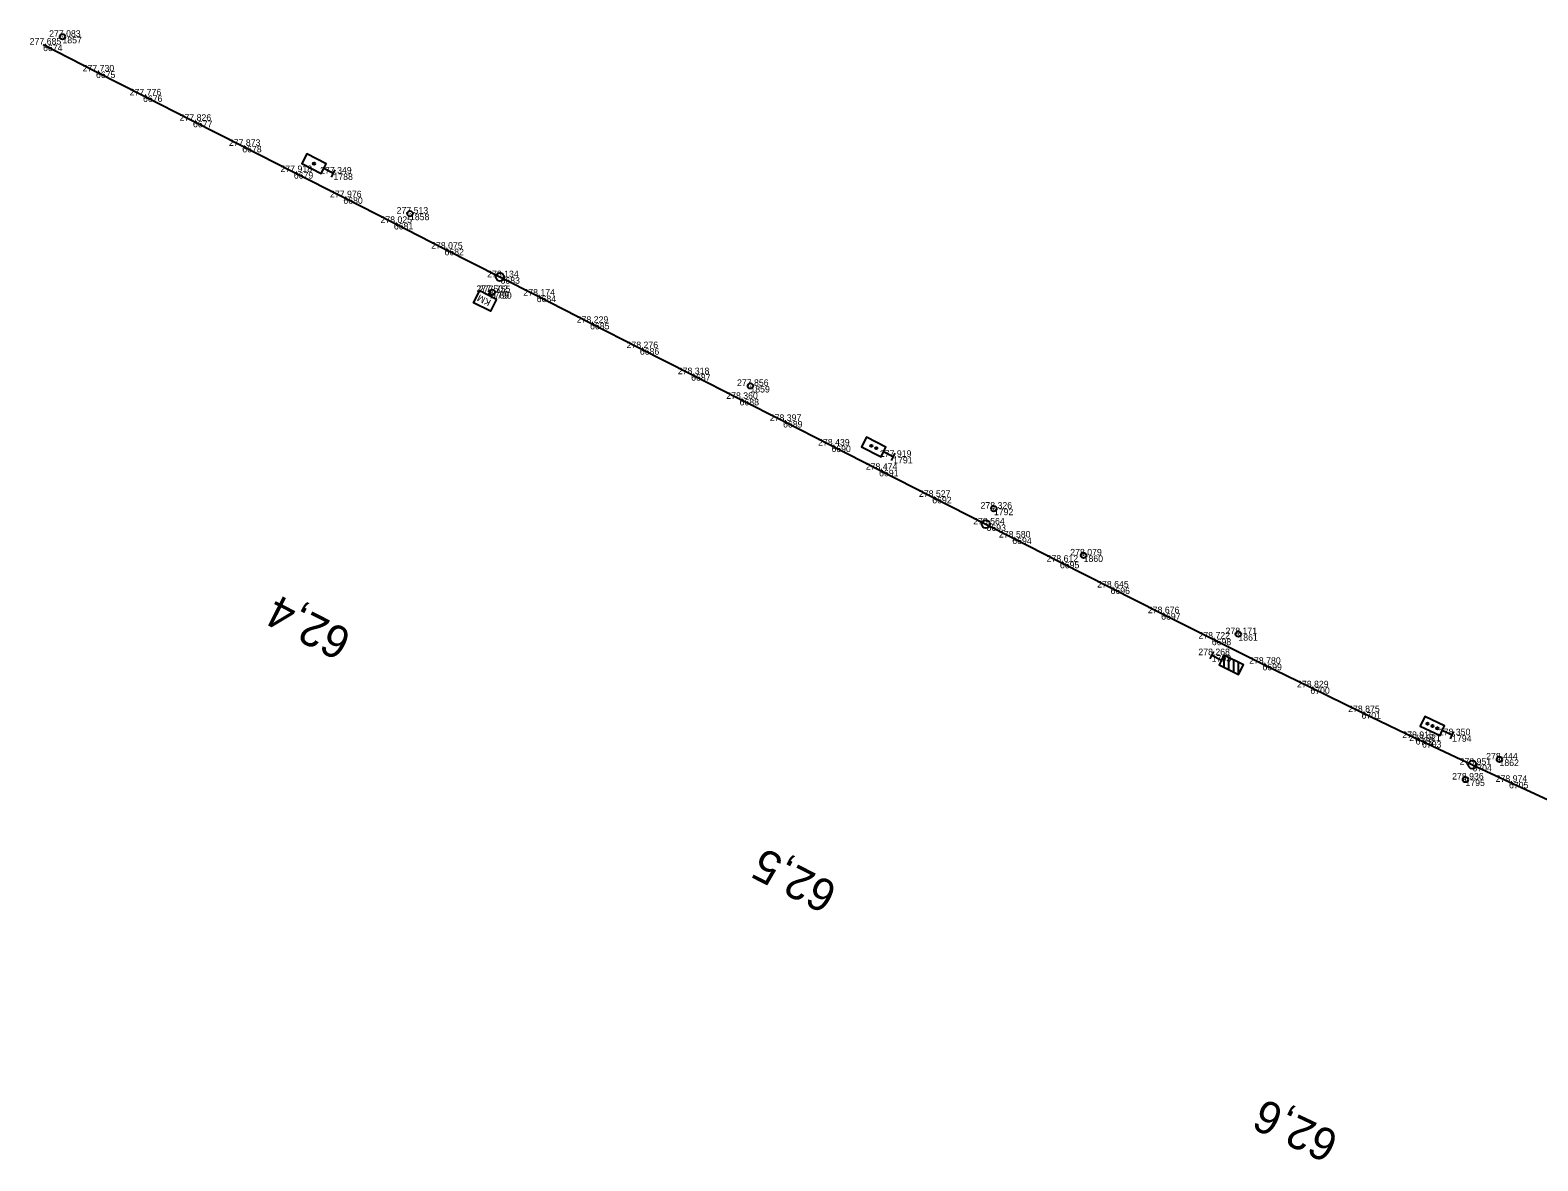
# Model space of a CAD drawing. Extents: x -613968 to -612840, y -1056667 to -1056202.
# Drawn here: x -613967.8 to -613690.5, y -1056410.2 to -1056202.3 of the extents above; entities that cross this region are included whole.
import ezdxf

# ---------------------------------------------------------------- set-up
doc = ezdxf.new("R2010")
doc.units = 0
for name, color, linetype in [('Rozpiska_pole_7', 7, 'Continuous'), ('Vrstva 1', 7, 'Continuous'), ('Vrstva 50', 7, 'Continuous'), ('Vrstva 60', 7, 'Continuous'), ('Vrstva 61', 7, 'Continuous')]:
    doc.layers.add(name, color=color, linetype=linetype)

msp = doc.modelspace()

# ---------------------------------------------------------------- linework, layer by layer
at = {"layer": 'Rozpiska_pole_7'}
for p, q in [((-613915.67, -1056226.63), (-613915.54, -1056227.01)), ((-613912.38, -1056229.3), (-613911.7, -1056227.97)), ((-613883.3, -1056250.41), (-613883.58, -1056250.96)), ((-613882.89, -1056250.43), (-613882.8, -1056250.47)), ((-613813.17, -1056278.5), (-613813.05, -1056278.88)), ((-613812.29, -1056278.96), (-613812.17, -1056279.34)), ((-613809.44, -1056281.4), (-613808.76, -1056280.06)), ((-613790.63, -1056290.23), (-613790.54, -1056290.28)), ((-613750.19, -1056316.52), (-613750.86, -1056317.86)), ((-613748.29, -1056317.18), (-613748.28, -1056319.42)), ((-613747.38, -1056319.86), (-613747.39, -1056317.63)), ((-613746.49, -1056318.07), (-613746.49, -1056320.31)), ((-613745.59, -1056320.75), (-613745.6, -1056318.52)), ((-613710.91, -1056329.59), (-613710.77, -1056329.97)), ((-613709.99, -1056330.02), (-613709.86, -1056330.39)), ((-613709.09, -1056330.44), (-613708.95, -1056330.82)), ((-613706.63, -1056332.59), (-613705.99, -1056331.23)), ((-613703.91, -1056340.03), (-613703.82, -1056340.07))]:
    msp.add_line(p, q, dxfattribs=at)
for points in [[(-613912.04, -1056228.64), (-613913.82, -1056227.73), (-613913.37, -1056226.84), (-613916.94, -1056225.02), (-613917.84, -1056226.81), (-613914.28, -1056228.62), (-613913.82, -1056227.73)], [(-613809.1, -1056280.73), (-613810.88, -1056279.82), (-613810.43, -1056278.93), (-613814, -1056277.12), (-613814.9, -1056278.9), (-613811.34, -1056280.72), (-613810.88, -1056279.82)], [(-613750.52, -1056317.19), (-613748.73, -1056318.08), (-613749.18, -1056318.97), (-613745.59, -1056320.75), (-613744.7, -1056318.96), (-613748.29, -1056317.18), (-613748.73, -1056318.08)], [(-613706.31, -1056331.91), (-613708.12, -1056331.05), (-613707.69, -1056330.15), (-613711.31, -1056328.45), (-613712.16, -1056330.25), (-613708.54, -1056331.96), (-613708.12, -1056331.05)]]:
    msp.add_lwpolyline(points, dxfattribs=at)
msp.add_lwpolyline([(-613882.03, -1056251.75), (-613883.16, -1056253.96), (-613886.27, -1056252.38), (-613885.14, -1056250.17)], close=True, dxfattribs=at)
for centre, radius in [((-613915.61, -1056226.82), 0.2), ((-613881.42, -1056247.65), 0.75), ((-613882.84, -1056250.45), 0.5), ((-613813.11, -1056278.69), 0.2), ((-613812.22, -1056279.14), 0.2), ((-613792.06, -1056293.09), 0.75), ((-613790.58, -1056290.25), 0.5), ((-613710.83, -1056329.78), 0.2), ((-613709.93, -1056330.2), 0.2), ((-613709.02, -1056330.63), 0.2), ((-613702.61, -1056337.33), 0.75), ((-613703.86, -1056340.05), 0.5)]:
    msp.add_circle(centre, radius, dxfattribs=at)
at = {"layer": 'Vrstva 1'}
msp.add_lwpolyline([(-613965.44, -1056204.93), (-613955.71, -1056209.87), (-613947.06, -1056214.27), (-613937.88, -1056218.94), (-613928.81, -1056223.55), (-613919.33, -1056228.37), (-613910.22, -1056233), (-613900.93, -1056237.72), (-613891.62, -1056242.46), (-613881.32, -1056247.7), (-613874.66, -1056251.08), (-613864.85, -1056256.08), (-613855.69, -1056260.74), (-613846.26, -1056265.53), (-613837.35, -1056270.06), (-613829.35, -1056274.13), (-613820.46, -1056278.65), (-613811.69, -1056283.11), (-613801.92, -1056288.08), (-613791.94, -1056293.16), (-613787.2, -1056295.56), (-613778.44, -1056300.01), (-613769.13, -1056304.75), (-613759.82, -1056309.47), (-613750.51, -1056314.15), (-613741.19, -1056318.77), (-613732.38, -1056323.1), (-613722.97, -1056327.66), (-613713.02, -1056332.42), (-613711.85, -1056332.98), (-613702.58, -1056337.34), (-613695.85, -1056340.48), (-613686.37, -1056344.84)], dxfattribs=at)
at = {"layer": 'Vrstva 50'}
for p, q in [((-613961.93, -1056203.47), (-613961.84, -1056203.52)), ((-613898.01, -1056235.99), (-613897.92, -1056236.04)), ((-613835.41, -1056267.67), (-613835.32, -1056267.71)), ((-613774.13, -1056298.83), (-613774.04, -1056298.87)), ((-613745.67, -1056313.3), (-613745.58, -1056313.34)), ((-613697.65, -1056336.34), (-613697.55, -1056336.38))]:
    msp.add_line(p, q, dxfattribs=at)
for centre in [(-613961.88, -1056203.5), (-613897.97, -1056236.01), (-613835.36, -1056267.69), (-613774.08, -1056298.85), (-613745.62, -1056313.32), (-613697.6, -1056336.36)]:
    msp.add_circle(centre, 0.5, dxfattribs=at)
at = {"layer": 'Vrstva 60'}
for p, q in [((-613961.88, -1056203.5), (-613961.88, -1056203.5)), ((-613965.44, -1056204.93), (-613965.44, -1056204.93)), ((-613955.71, -1056209.87), (-613955.71, -1056209.87)), ((-613947.06, -1056214.27), (-613947.06, -1056214.27)), ((-613937.88, -1056218.94), (-613937.88, -1056218.94)), ((-613928.81, -1056223.55), (-613928.81, -1056223.55)), ((-613919.33, -1056228.37), (-613919.33, -1056228.37)), ((-613912.04, -1056228.64), (-613912.04, -1056228.64)), ((-613910.22, -1056233), (-613910.22, -1056233)), ((-613897.97, -1056236.01), (-613897.97, -1056236.01)), ((-613900.93, -1056237.72), (-613900.93, -1056237.72)), ((-613891.62, -1056242.46), (-613891.62, -1056242.46)), ((-613881.32, -1056247.7), (-613881.32, -1056247.7)), ((-613883.3, -1056250.41), (-613883.3, -1056250.41)), ((-613882.84, -1056250.45), (-613882.84, -1056250.45)), ((-613874.66, -1056251.08), (-613874.66, -1056251.08)), ((-613864.85, -1056256.08), (-613864.85, -1056256.08)), ((-613855.69, -1056260.74), (-613855.69, -1056260.74)), ((-613846.26, -1056265.53), (-613846.26, -1056265.53)), ((-613837.35, -1056270.06), (-613837.35, -1056270.06)), ((-613835.36, -1056267.69), (-613835.36, -1056267.69)), ((-613829.35, -1056274.13), (-613829.35, -1056274.13)), ((-613820.46, -1056278.65), (-613820.46, -1056278.65)), ((-613809.1, -1056280.73), (-613809.1, -1056280.73)), ((-613811.69, -1056283.11), (-613811.69, -1056283.11)), ((-613801.92, -1056288.08), (-613801.92, -1056288.08)), ((-613790.58, -1056290.25), (-613790.58, -1056290.25)), ((-613791.94, -1056293.16), (-613791.94, -1056293.16)), ((-613787.2, -1056295.56), (-613787.2, -1056295.56)), ((-613778.44, -1056300.01), (-613778.44, -1056300.01)), ((-613774.08, -1056298.85), (-613774.08, -1056298.85)), ((-613769.13, -1056304.75), (-613769.13, -1056304.75)), ((-613759.82, -1056309.47), (-613759.82, -1056309.47)), ((-613750.51, -1056314.15), (-613750.51, -1056314.15)), ((-613745.62, -1056313.32), (-613745.62, -1056313.32)), ((-613750.52, -1056317.19), (-613750.52, -1056317.19)), ((-613741.19, -1056318.77), (-613741.19, -1056318.77)), ((-613732.38, -1056323.1), (-613732.38, -1056323.1)), ((-613722.97, -1056327.66), (-613722.97, -1056327.66)), ((-613713.02, -1056332.42), (-613713.02, -1056332.42)), ((-613711.85, -1056332.98), (-613711.85, -1056332.98)), ((-613706.31, -1056331.91), (-613706.31, -1056331.91)), ((-613697.6, -1056336.36), (-613697.6, -1056336.36)), ((-613702.58, -1056337.34), (-613702.58, -1056337.34)), ((-613703.86, -1056340.05), (-613703.86, -1056340.05)), ((-613695.85, -1056340.48), (-613695.85, -1056340.48))]:
    msp.add_line(p, q, dxfattribs=at)

# ---------------------------------------------------------------- texts
at = {"layer": 'Rozpiska_pole_7'}
for s, height, rotation, p in [('KM', 1.247, 153.0609, (-613882.96, -1056251.97)), ('62,4', 6, 153.0609, (-613908.34, -1056313.01)), ('62,5', 6, 153.0346, (-613819.01, -1056359.54)), ('62,6', 6, 154.7757, (-613726.8, -1056405.26))]:
    msp.add_text(s, height=height, rotation=rotation, dxfattribs=at).set_placement(p)
at = {"layer": 'Vrstva 60'}
for s, p in [('1857', (-613961.88, -1056204.7)), ('6674', (-613965.44, -1056206.13)), ('6675', (-613955.71, -1056211.07)), ('6676', (-613947.06, -1056215.47)), ('6677', (-613937.88, -1056220.14)), ('6678', (-613928.81, -1056224.75)), ('6679', (-613919.33, -1056229.57)), ('1788', (-613912.04, -1056229.83)), ('6680', (-613910.22, -1056234.2)), ('1858', (-613897.97, -1056237.21)), ('6681', (-613900.93, -1056238.92)), ('6682', (-613891.62, -1056243.66)), ('6683', (-613881.32, -1056248.9)), ('1789', (-613883.3, -1056251.61)), ('1790', (-613882.84, -1056251.65)), ('6684', (-613874.66, -1056252.28)), ('6685', (-613864.85, -1056257.28)), ('6686', (-613855.69, -1056261.94)), ('6687', (-613846.26, -1056266.73)), ('6688', (-613837.35, -1056271.26)), ('1859', (-613835.36, -1056268.89)), ('6689', (-613829.35, -1056275.33)), ('6690', (-613820.46, -1056279.85)), ('1791', (-613809.1, -1056281.93)), ('6691', (-613811.69, -1056284.31)), ('6692', (-613801.92, -1056289.28)), ('1792', (-613790.58, -1056291.45)), ('6693', (-613791.94, -1056294.36)), ('6694', (-613787.2, -1056296.76)), ('6695', (-613778.44, -1056301.21)), ('1860', (-613774.08, -1056300.05)), ('6696', (-613769.13, -1056305.95)), ('6697', (-613759.82, -1056310.67)), ('6698', (-613750.51, -1056315.35)), ('1861', (-613745.62, -1056314.52)), ('1793', (-613750.52, -1056318.39)), ('6699', (-613741.19, -1056319.97)), ('6700', (-613732.38, -1056324.3)), ('6701', (-613722.97, -1056328.86)), ('6702', (-613713.02, -1056333.62)), ('6703', (-613711.85, -1056334.18)), ('1794', (-613706.31, -1056333.11)), ('1862', (-613697.6, -1056337.56)), ('6704', (-613702.58, -1056338.54)), ('1795', (-613703.86, -1056341.25)), ('6705', (-613695.85, -1056341.68))]:
    msp.add_text(s, height=1.2, dxfattribs=at).set_placement(p)
at = {"layer": 'Vrstva 61'}
for s, p in [('277.685', (-613967.9, -1056204.93)), ('277.083', (-613964.33, -1056203.5)), ('277.730', (-613958.16, -1056209.87)), ('277.776', (-613949.51, -1056214.27)), ('277.826', (-613940.33, -1056218.94)), ('277.873', (-613931.27, -1056223.55)), ('277.918', (-613921.78, -1056228.37)), ('277.349', (-613914.49, -1056228.64)), ('277.976', (-613912.67, -1056233)), ('278.025', (-613903.39, -1056237.72)), ('277.513', (-613900.42, -1056236.01)), ('278.075', (-613894.08, -1056242.46)), ('278.134', (-613883.77, -1056247.7)), ('277.502', (-613885.75, -1056250.41)), ('277.755', (-613885.3, -1056250.45)), ('278.174', (-613877.11, -1056251.08)), ('278.229', (-613867.3, -1056256.08)), ('278.276', (-613858.14, -1056260.74)), ('278.318', (-613848.71, -1056265.53)), ('277.856', (-613837.82, -1056267.69)), ('278.360', (-613839.8, -1056270.06)), ('278.397', (-613831.8, -1056274.13)), ('278.439', (-613822.91, -1056278.65)), ('277.919', (-613811.55, -1056280.73)), ('278.474', (-613814.14, -1056283.11)), ('278.527', (-613804.37, -1056288.08)), ('278.326', (-613793.04, -1056290.25)), ('278.564', (-613794.39, -1056293.16)), ('278.580', (-613789.65, -1056295.56)), ('278.079', (-613776.54, -1056298.85)), ('278.612', (-613780.89, -1056300.01)), ('278.645', (-613771.59, -1056304.75)), ('278.676', (-613762.27, -1056309.47)), ('278.722', (-613752.96, -1056314.15)), ('278.171', (-613747.98, -1056313.32)), ('278.268', (-613752.98, -1056317.19)), ('278.780', (-613743.64, -1056318.77)), ('278.829', (-613734.83, -1056323.1)), ('278.875', (-613725.43, -1056327.66)), ('278.915', (-613715.47, -1056332.42)), ('278.350', (-613708.76, -1056331.91)), ('278.921', (-613714.2, -1056332.98)), ('278.951', (-613704.94, -1056337.34)), ('278.444', (-613700.05, -1056336.36)), ('278.936', (-613706.31, -1056340.05)), ('278.974', (-613698.3, -1056340.48))]:
    msp.add_text(s, height=1.2, dxfattribs=at).set_placement(p)

doc.saveas('drawing.dxf')
